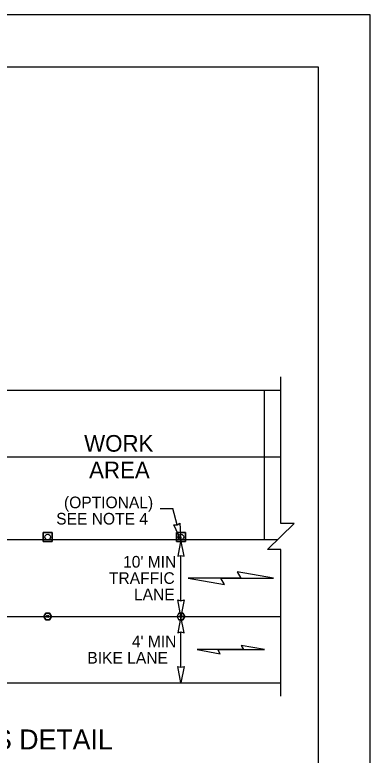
# Model space of a CAD drawing. Extents: x 99999.1 to 100095.7, y 99995 to 100010.7.
# Drawn here: x 100073.928 to 100076.062, y 100006.235 to 100010.687 of the extents above; entities that cross this region are included whole.
import ezdxf

# ---------------------------------------------------------------- set-up
doc = ezdxf.new("R2010")
doc.units = 0
for name, color, linetype in [('RD_ED_ShoulderPavedEdge', 7, 'Continuous'), ('RD_MK_LineEdgeWhite', 7, 'Continuous'), ('RD_MK_LineSkipCenter', 7, 'Continuous'), ('SH_DE_DetailHeading2Text', 7, 'Continuous'), ('SH_GI_PlotLimits', 7, 'Continuous'), ('SH_GI_SheetBorder', 7, 'Continuous'), ('TR_WZ_TrafficCone', 7, 'Continuous'), ('TR_WZ_TubularMarker', 7, 'Continuous'), ('TR_WZ_WorkAreaLabel', 7, 'Continuous'), ('TR_WZ_WorkZoneDetails', 7, 'Continuous'), ('TR_WZ_WorkZoneTextCurrent', 7, 'Continuous')]:
    doc.layers.add(name, color=color, linetype=linetype)

msp = doc.modelspace()

# ---------------------------------------------------------------- linework, layer by layer
at = {"layer": 'RD_ED_ShoulderPavedEdge'}
for p, q in [((100073.725, 100008.4305), (100075.525, 100008.4305)), ((100070.725, 100006.6704), (100075.525, 100006.6704))]:
    msp.add_line(p, q, dxfattribs=at)
at = {"layer": 'RD_MK_LineEdgeWhite'}
for p, q in [((100070.725, 100008.0305), (100075.525, 100008.0305)), ((100070.725, 100007.0704), (100075.525, 100007.0704))]:
    msp.add_line(p, q, dxfattribs=at)
at = {"layer": 'RD_MK_LineSkipCenter'}
msp.add_lwpolyline([(100075.5043, 100007.5305), (100070.7043, 100007.5305)], dxfattribs=at)
at = {"layer": 'SH_GI_PlotLimits'}
msp.add_lwpolyline([(100059.0625, 99999.6875), (100076.0625, 99999.6875), (100076.0625, 100010.6875), (100059.0625, 100010.6875)], close=True, dxfattribs=at)
at = {"layer": 'SH_GI_SheetBorder'}
for p, q in [((100060, 100010.375), (100075.75, 100010.375)), ((100075.75, 100010.375), (100075.75, 100000))]:
    msp.add_line(p, q, dxfattribs=at)
at = {"layer": 'TR_WZ_TrafficCone'}
for points in [[(100074.099, 100007.5738), (100074.1524, 100007.5738), (100074.1524, 100007.5205), (100074.099, 100007.5205), (100074.099, 100007.5738)], [(100074.099, 100007.5205), (100074.1524, 100007.5205), (100074.1524, 100007.5738), (100074.099, 100007.5738), (100074.099, 100007.5205)], [(100074.899, 100007.5738), (100074.9524, 100007.5738), (100074.9524, 100007.5205), (100074.899, 100007.5205), (100074.899, 100007.5738)], [(100074.899, 100007.5205), (100074.9524, 100007.5205), (100074.9524, 100007.5738), (100074.899, 100007.5738), (100074.899, 100007.5205)]]:
    msp.add_lwpolyline(points, dxfattribs=at)
for centre in [(100074.1257, 100007.5471), (100074.9257, 100007.5471)]:
    msp.add_circle(centre, 0.0167, dxfattribs=at)
at = {"layer": 'TR_WZ_TubularMarker'}
for points in [[(100074.1026, 100007.0704), (100074.1141, 100007.0905), (100074.1372, 100007.0905), (100074.1488, 100007.0704), (100074.1372, 100007.0504), (100074.1141, 100007.0504)], [(100074.9026, 100007.0704), (100074.9141, 100007.0905), (100074.9372, 100007.0905), (100074.9488, 100007.0704), (100074.9372, 100007.0504), (100074.9141, 100007.0504)]]:
    msp.add_lwpolyline(points, close=True, dxfattribs=at)
for points in [[(100074.1141, 100007.0504), (100074.1372, 100007.0504), (100074.1488, 100007.0704), (100074.1372, 100007.0905), (100074.1141, 100007.0905), (100074.1026, 100007.0704), (100074.1141, 100007.0504)], [(100074.9141, 100007.0504), (100074.9372, 100007.0504), (100074.9488, 100007.0704), (100074.9372, 100007.0905), (100074.9141, 100007.0905), (100074.9026, 100007.0704), (100074.9141, 100007.0504)]]:
    msp.add_lwpolyline(points, dxfattribs=at)
for centre in [(100074.1257, 100007.0704), (100074.9257, 100007.0704)]:
    msp.add_circle(centre, 0.00667, dxfattribs=at)
at = {"layer": 'TR_WZ_WorkZoneDetails'}
for p, q in [((100074.8007, 100007.7185), (100074.8769, 100007.7185)), ((100074.9022, 100007.6212), (100074.8769, 100007.7185)), ((100074.9256, 100007.1642), (100074.9256, 100007.4367)), ((100075.2856, 100007.3005), (100075.0445, 100007.3005)), ((100075.1651, 100007.3005), (100075.4062, 100007.3005)), ((100074.9256, 100006.7642), (100074.9256, 100006.9767)), ((100075.3025, 100006.8704), (100075.1482, 100006.8704)), ((100075.1482, 100006.8704), (100075.3025, 100006.8704))]:
    msp.add_line(p, q, dxfattribs=at)
msp.add_lwpolyline([(100075.525, 100006.5904), (100075.525, 100007.473), (100075.445, 100007.473), (100075.605, 100007.6279), (100075.525, 100007.6279), (100075.525, 100008.5105)], dxfattribs=at)
for points in [[(100075.425, 100008.4305), (100075.425, 100008.0305), (100075.425, 100007.5305), (100074.501, 100007.5305), (100074.501, 100007.5305), (100074.501, 100007.5305), (100073.7257, 100007.5305), (100073.7257, 100007.5305), (100073.7257, 100007.5305), (100073.529, 100007.5814), (100073.3852, 100007.7182), (100073.311, 100007.8771), (100073.3017, 100008.0071), (100073.3017, 100008.2071), (100073.3017, 100008.4305)], [(100074.9257, 100007.5305), (100074.8824, 100007.6208), (100074.9022, 100007.6212), (100074.9197, 100007.6304)], [(100074.9257, 100007.5305), (100074.9064, 100007.4322), (100074.9257, 100007.4367), (100074.945, 100007.4322)], [(100075.4821, 100007.3005), (100075.2633, 100007.339), (100075.2856, 100007.3005)], [(100074.9685, 100007.3005), (100075.1873, 100007.2619), (100075.1651, 100007.3005)], [(100074.9256, 100007.0704), (100074.9064, 100007.1687), (100074.9256, 100007.1642), (100074.9449, 100007.1687)], [(100074.9256, 100007.0704), (100074.9064, 100006.9722), (100074.9256, 100006.9767), (100074.9449, 100006.9722)], [(100075.0224, 100006.8704), (100075.1624, 100006.8458), (100075.1482, 100006.8704)], [(100075.4283, 100006.8704), (100075.2882, 100006.8951), (100075.3025, 100006.8704)], [(100074.9256, 100006.6704), (100074.9064, 100006.7687), (100074.9256, 100006.7642), (100074.9449, 100006.7687)]]:
    msp.add_lwpolyline(points, close=True, dxfattribs=at)

# ---------------------------------------------------------------- texts
at = {"layer": 'SH_DE_DetailHeading2Text'}
msp.add_text('DRIVEWAY OR BUSINESS ACCESS DETAIL', height=0.12, rotation=360, dxfattribs=at).set_placement((100071.2082, 100006.2704))
at = {"layer": 'TR_WZ_WorkAreaLabel'}
for s, p in [('WORK', (100074.3444, 100008.0605)), ('AREA', (100074.3741, 100007.9004))]:
    msp.add_text(s, height=0.1, dxfattribs=at).set_placement(p)
at = {"layer": 'TR_WZ_WorkZoneTextCurrent'}
for s, p in [('(OPTIONAL)', (100074.2233, 100007.7205)), ('SEE NOTE 4', (100074.1764, 100007.6225)), ("10' MIN", (100074.5783, 100007.3635)), ('TRAFFIC', (100074.4933, 100007.2655)), ('LANE', (100074.6437, 100007.1675)), ("4' MIN", (100074.6312, 100006.8844)), ('BIKE LANE', (100074.3637, 100006.7864))]:
    msp.add_text(s, height=0.07, dxfattribs=at).set_placement(p)

doc.saveas('drawing.dxf')
